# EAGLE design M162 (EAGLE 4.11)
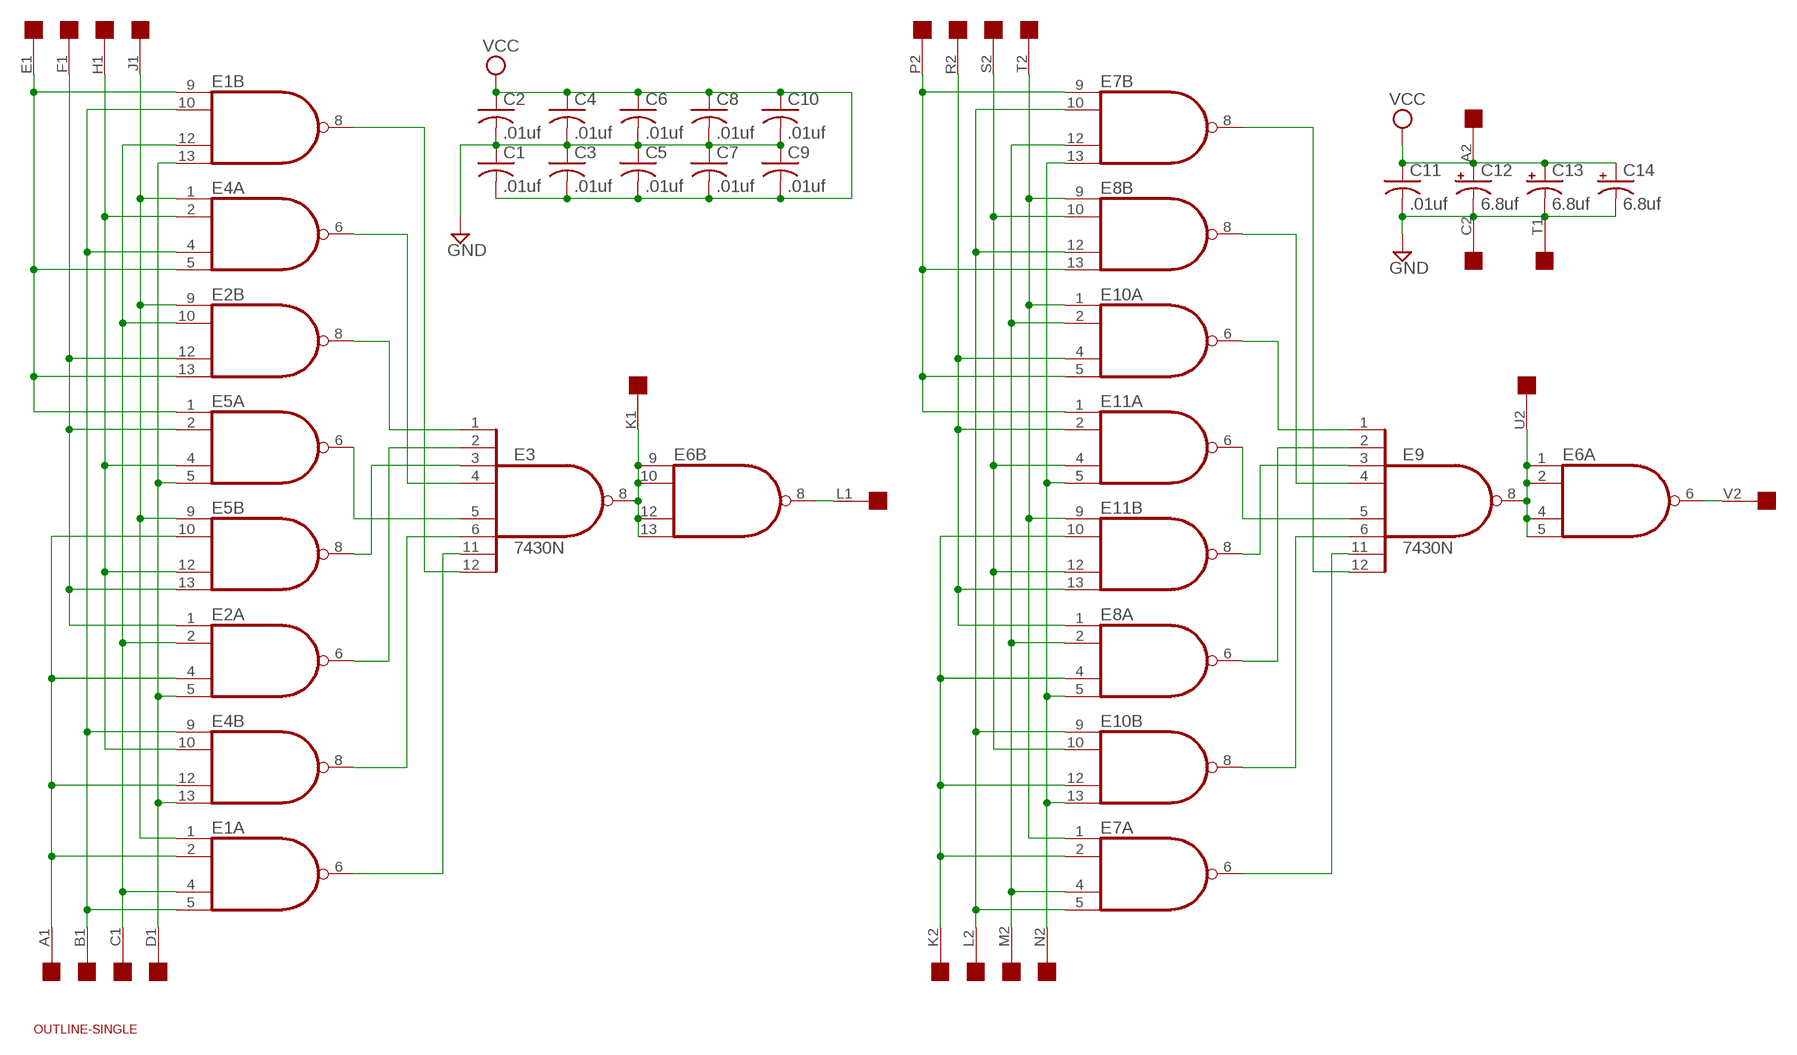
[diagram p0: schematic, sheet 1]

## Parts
C1  .01uf  C-US050-025X075  [C050-025X075]
C2  .01uf  C-US050-025X075  [C050-025X075]
C3  .01uf  C-US050-025X075  [C050-025X075]
C4  .01uf  C-US050-025X075  [C050-025X075]
C5  .01uf  C-US050-025X075  [C050-025X075]
C6  .01uf  C-US050-025X075  [C050-025X075]
C7  .01uf  C-US050-025X075  [C050-025X075]
C8  .01uf  C-US050-025X075  [C050-025X075]
C9  .01uf  C-US050-025X075  [C050-025X075]
C10  .01uf  C-US050-025X075  [C050-025X075]
C11  .01uf  C-US050-025X075  [C050-025X075]
C12  6.8uf  CPOL-USE22-6AXIAL  [E22-6]
C13  6.8uf  CPOL-USE22-6AXIAL  [E22-6]
C14  6.8uf  CPOL-USE22-6AXIAL  [E22-6]
E1  74S20N  [DIL14]
E2  74S20N  [DIL14]
E3  7430N  [DIL14]
E4  74S20N  [DIL14]
E5  74S20N  [DIL14]
E6  74S20N  [DIL14]
E7  74S20N  [DIL14]
E8  74S20N  [DIL14]
E9  7430N  [DIL14]
E10  74S20N  [DIL14]
E11  74S20N  [DIL14]
U$1  OUTLINE-SINGLE  [SINGLE]
U$2  EDGE-2CONNECTOR  [EDGE-CON2]

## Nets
GND: C1.1 C2.2 C3.1 C4.2 C5.1 C6.2 C7.1 C8.2 C9.1 C10.2 C11.2 C12.- C13.- C14.- U$2.C2 U$2.T1
N$1: E1.2(A:I1) E2.4(A:I2) E4.12(B:I2) E5.10(B:I1) U$2.A1
N$2: E1.13(B:I3) E2.5(A:I3) E4.13(B:I3) E5.5(A:I3) U$2.D1
N$3: E1.1(A:I0) E2.9(B:I0) E4.1(A:I0) E5.9(B:I0) U$2.J1
N$4: E4.2(A:I1) E4.10(B:I1) E5.4(A:I2) E5.12(B:I2) U$2.H1
N$5: E1.4(A:I2) E1.12(B:I2) E2.2(A:I1) E2.10(B:I1) U$2.C1
N$6: E1.5(A:I3) E1.10(B:I1) E4.4(A:I2) E4.9(B:I0) U$2.B1
N$7: E2.1(A:I0) E2.12(B:I2) E5.2(A:I1) E5.13(B:I3) U$2.F1
N$8: E1.9(B:I0) E2.13(B:I3) E4.5(A:I3) E5.1(A:I0) U$2.E1
N$9: E1.8(B:O) E3.12(I7)
N$10: E3.4(I3) E4.6(A:O)
N$11: E2.8(B:O) E3.1(I0)
N$12: E3.5(I4) E5.6(A:O)
N$13: E3.3(I2) E5.8(B:O)
N$14: E2.6(A:O) E3.2(I1)
N$15: E1.6(A:O) E3.11(I6)
N$16: E3.6(I5) E4.8(B:O)
N$17: E3.8(O) E6.9(B:I0) E6.10(B:I1) E6.12(B:I2) E6.13(B:I3) U$2.K1
N$18: E7.2(A:I1) E8.4(A:I2) E10.12(B:I2) E11.10(B:I1) U$2.K2
N$19: E7.13(B:I3) E8.5(A:I3) E10.13(B:I3) E11.5(A:I3) U$2.N2
N$20: E7.1(A:I0) E8.9(B:I0) E10.1(A:I0) E11.9(B:I0) U$2.T2
N$21: E8.10(B:I1) E10.10(B:I1) E11.4(A:I2) E11.12(B:I2) U$2.S2
N$22: E7.4(A:I2) E7.12(B:I2) E8.2(A:I1) E10.2(A:I1) U$2.M2
N$23: E7.5(A:I3) E7.10(B:I1) E8.12(B:I2) E10.9(B:I0) U$2.L2
N$24: E8.1(A:I0) E10.4(A:I2) E11.2(A:I1) E11.13(B:I3) U$2.R2
N$25: E7.9(B:I0) E8.13(B:I3) E10.5(A:I3) E11.1(A:I0) U$2.P2
N$26: E7.8(B:O) E9.12(I7)
N$27: E8.8(B:O) E9.4(I3)
N$28: E9.1(I0) E10.6(A:O)
N$29: E9.5(I4) E11.6(A:O)
N$30: E9.3(I2) E11.8(B:O)
N$31: E8.6(A:O) E9.2(I1)
N$32: E7.6(A:O) E9.11(I6)
N$33: E9.6(I5) E10.8(B:O)
N$34: E6.1(A:I0) E6.2(A:I1) E6.4(A:I2) E6.5(A:I3) E9.8(O) U$2.U2
N$35: E6.6(A:O) U$2.V2
N$36: E6.8(B:O) U$2.L1
VCC: C1.2 C2.1 C3.2 C4.1 C5.2 C6.1 C7.2 C8.1 C9.2 C10.1 C11.1 C12.+ C13.+ C14.+ U$2.A2
Unconnected: U$2.B2 U$2.D2 U$2.E2 U$2.F2 U$2.H2 U$2.J2 U$2.M1 U$2.N1 U$2.P1 U$2.R1 U$2.S1 U$2.U1 U$2.V1

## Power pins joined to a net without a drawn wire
GND: E1.7(P:GND) E2.7(P:GND) E3.7(GND) E4.7(P:GND) E5.7(P:GND) E6.7(P:GND) E7.7(P:GND) E8.7(P:GND) E9.7(GND) E10.7(P:GND) E11.7(P:GND)
VCC: E1.14(P:VCC) E2.14(P:VCC) E3.14(VCC) E4.14(P:VCC) E5.14(P:VCC) E6.14(P:VCC) E7.14(P:VCC) E8.14(P:VCC) E9.14(VCC) E10.14(P:VCC) E11.14(P:VCC)

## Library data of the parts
C1-C11 = rcl:C-US: CAPACITOR, American symbol
C12-C14 = rcl:CPOL-US: POLARIZED CAPACITOR, American symbol
E1 E2 E4-E8 E10 E11 = 74xx-jameco:74*20: Dual 4-input NAND gate
E3 E9 = 74xx-jameco:74*30: 8-input NAND gate
U$1 = dec-con:OUTLINE-*: Board outlines for DEC boards.
U$2 = dec-con:EDGE-2: Double-Sided DEC edge connector.

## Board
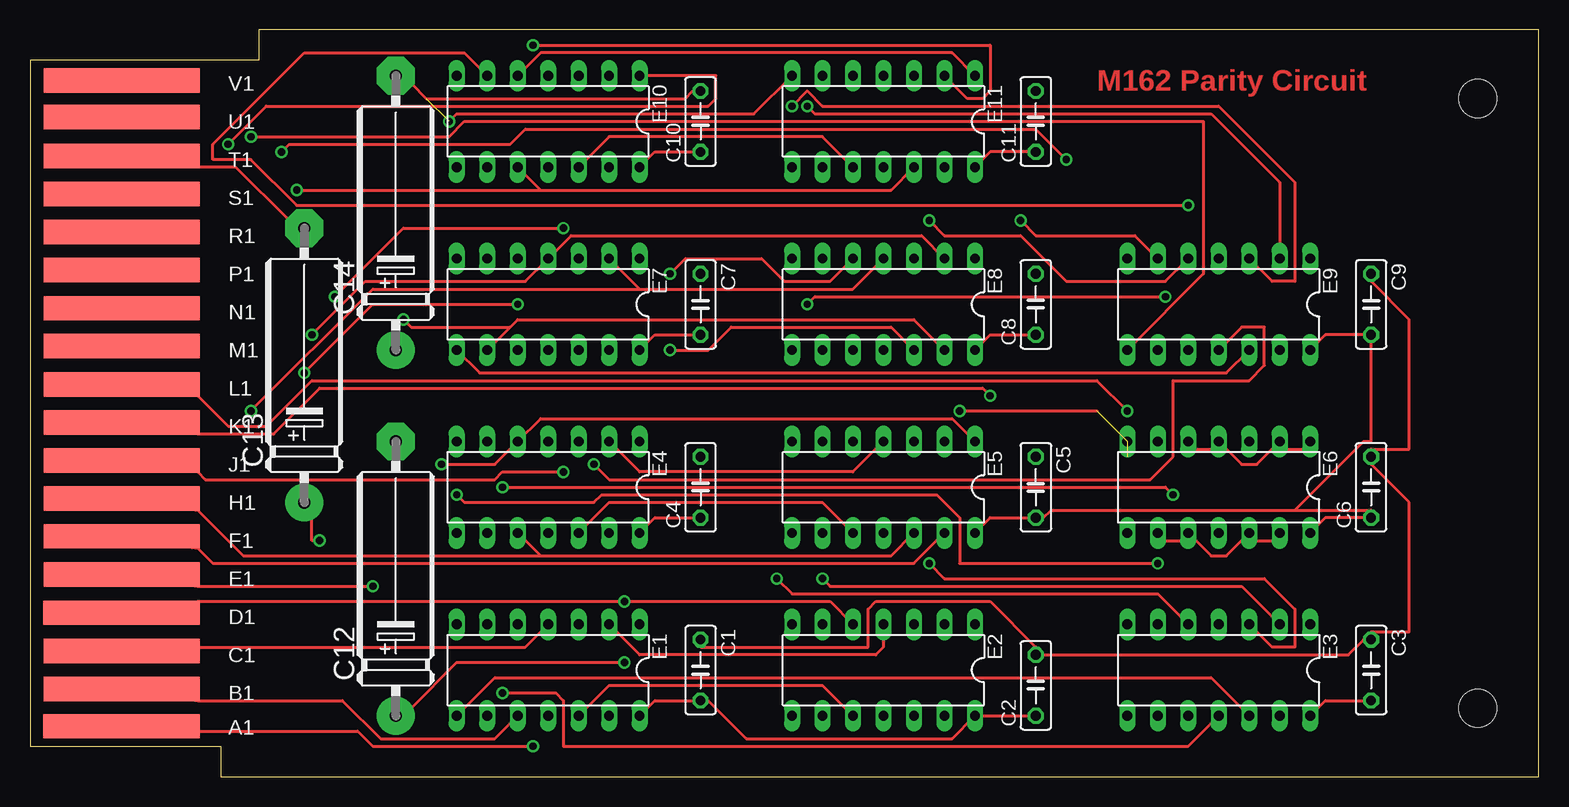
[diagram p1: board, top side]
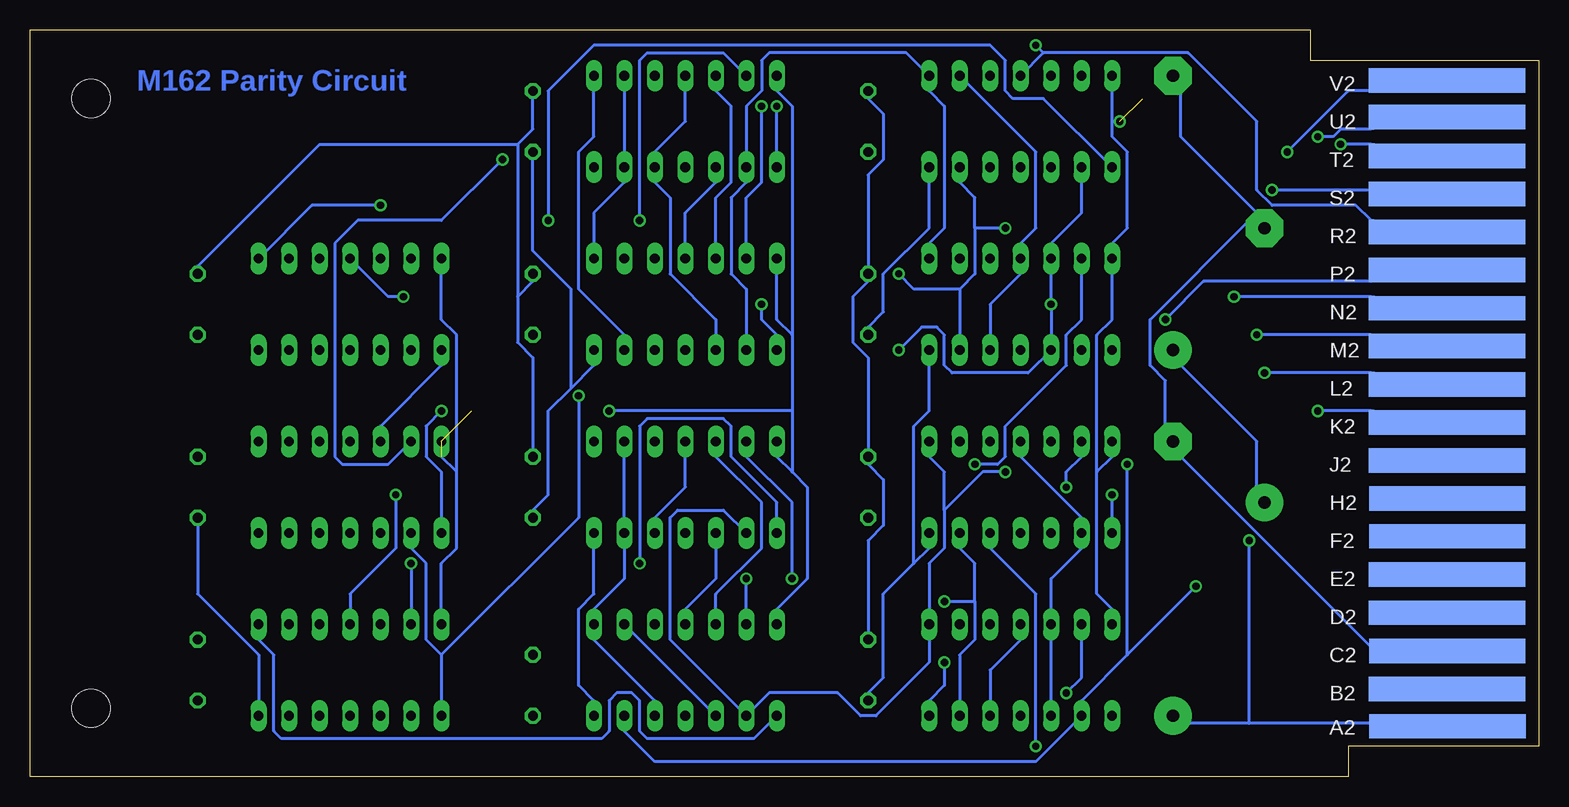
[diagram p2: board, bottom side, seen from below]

Size 125.73 x 62.23 mm. Coordinates in mm from the lower left corner, seen from the top.
Copper layers (1*16): Top 0.035mm / dielectric 1.5mm / Bottom 0.035mm
Design rules "default": minimum track width 10mil, minimum drill 24mil, track to track 8mil, track to pad 8mil, pad to pad 8mil, via to via 8mil, smd to smd 8mil, copper to edge 25mil, drill to drill 8mil, minimum pad ring 10mil, minimum via ring 8mil, stop-mask expansion 4mil, vias tented up to drill 0mil, thermal gap 10mil

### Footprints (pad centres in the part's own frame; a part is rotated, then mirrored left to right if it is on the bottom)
C050-025X075 = drill 0.813 octagon: 1 -2.54,0; 2 2.54,0
E22-6 = drill 1.016 pad 3.15 round: + -11.43,0 | drill 1.016 pad 3.15 octagon: - 11.43,0
DIL14 = drill 0.813 long: 1 -7.62,-3.81; 2 -5.08,-3.81; 3 -2.54,-3.81; 4 0,-3.81; 5 2.54,-3.81; 6 5.08,-3.81; 7 7.62,-3.81; 8 7.62,3.81; 9 5.08,3.81; 10 2.54,3.81; 11 0,3.81; 12 -2.54,3.81; 13 -5.08,3.81; 14 -7.62,3.81
SINGLE = hole 3.175: 120.65,56.515; 120.65,5.715
EDGE-CON2 = smd 13.017 x 2.032: A1 7.633,4.207; B1 7.639,7.327; C1 7.636,10.489; D1 7.633,13.665; E1 7.642,16.84; F1 7.642,20.041; H1 7.642,23.19; J1 7.642,26.34; K1 7.642,29.515; L1 7.642,32.69; M1 7.642,35.89; N1 7.642,39.04; P1 7.642,42.24; R1 7.642,45.39; S1 7.642,48.565; T1 7.642,51.74; U1 7.642,54.966; V1 7.642,58.026 | smd 13.017 x 2.032 bottom: A2 7.614,4.207; B2 7.642,7.328; C2 7.617,10.49; D2 7.642,13.665; E2 7.642,16.84; F2 7.617,20.041; H2 7.617,23.19; J2 7.642,26.34; K2 7.642,29.515; L2 7.642,32.69; M2 7.642,35.89; N2 7.642,39.04; P2 7.642,42.24; R2 7.642,45.39; S2 7.642,48.565; T2 7.642,51.74; U2 7.642,54.966; V2 7.642,58.026

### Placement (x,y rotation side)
C1  55.88,8.89 270 top
C2  83.82,7.62 90 top
C3  111.76,8.89 270 top
C4  55.88,24.13 90 top
C5  83.82,24.13 270 top
C6  111.76,24.13 90 top
C7  55.88,39.37 270 top
C8  83.82,39.37 90 top
C9  111.76,39.37 270 top
C10  55.88,54.61 90 top
C11  83.82,54.61 90 top
C12  30.48,16.51 90 top
C13  22.86,34.29 90 top
C14  30.48,46.99 90 top
E1  43.18,8.89 180 top
E2  71.12,8.89 180 top
E3  99.06,8.89 180 top
E4  43.18,24.13 180 top
E5  71.12,24.13 180 top
E6  99.06,24.13 180 top
E7  43.18,39.37 180 top
E8  71.12,39.37 180 top
E9  99.06,39.37 180 top
E10  43.18,54.61 180 top
E11  71.12,54.61 180 top
U$1  0,0 0 top
U$2  0,0 0 top

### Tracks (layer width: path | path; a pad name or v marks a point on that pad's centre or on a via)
GND  (via drill 0.61)  (3 unrouted)
  Top 0.254: C9.1 111.76,41.27 114.94,38.1 114.94,27.3 111.76,27.3 C6.2 111.76,26.04 114.94,22.86 114.94,12.06 111.76,12.06 C3.1 111.13,11.43 109.86,10.16 C2.2 83.82,10.79 80.01,14.61 70.49,14.61 69.85,13.97 69.85,10.79 55.88,10.79 C1.1 | C13.- 21.59,46.35 17.15,50.8 13.97,50.8 U$2.T1 | C10.2 55.25,57.15 54.61,56.52 33.02,56.52 31.75,57.78 C14.- | v77.47,30.48 88.9,30.48 | v34.93,54.61 35.56,55.24 60.33,55.24 E11.7
  Bottom 0.254: 85.09,40.01 85.09,36.2 83.82,34.92 C5.1 | 85.09,40.01 83.82,41.27 C8.2 | 85.09,52.7 83.82,53.98 C11.2 | 85.09,52.7 85.09,40.01 | 85.09,52.7 101.6,52.7 111.76,42.55 C9.1 | U$2.C2 13.97,10.79 29.85,26.67 C12.- 31.12,29.21 31.12,33.02 32.39,34.29 32.39,38.1 24.13,46.35 C13.- 23.5,46.99 29.85,53.34 29.85,57.15 C14.- | C1.1 55.88,19.68 54.61,20.95 54.61,24.77 55.88,26.04 C4.2 55.88,34.92 57.15,36.2 57.15,40.01 55.88,41.27 C7.1 55.88,50.16 54.61,51.44 54.61,55.24 55.88,56.52 C10.2 | 36.83,25.4 36.83,15.24 35.56,13.97 E1.7 | 36.83,25.4 35.56,26.67 E4.7 | 36.83,25.4 36.83,36.83 35.56,38.1 E7.7 35.56,44.45 34.29,45.72 34.29,52.07 35.56,53.34 35.56,54.61 | 35.56,54.61 E10.7 | 90.17,25.4 90.17,19.05 91.44,17.78 E3.7 | 90.17,25.4 91.44,26.67 | 90.17,25.4 90.17,36.83 91.44,38.1 E9.7 | 62.23,25.4 63.5,26.67 E5.7 | 62.23,25.4 60.96,24.13 60.96,16.51 63.5,13.97 E2.7 | 62.23,36.83 63.5,38.1 E8.7 | 62.23,30.48 62.23,25.4 | 62.23,36.83 62.23,30.48 | 62.23,36.83 62.23,55.88 63.5,57.15 E11.7 | 62.23,30.48 v77.47,30.48 | 35.56,54.61 v34.93,54.61
N$1  (via drill 0.61)
  Top 0.254: E4.12 48.26,22.86 66.04,22.86 E5.10 | E1.2 50.8,10.16 70.49,10.16 71.12,10.79 E2.4 | v41.91,2.54 28.58,2.54 27.31,3.81 13.97,3.81 U$2.A1
  Bottom 0.254: E5.10 68.58,16.51 71.12,13.97 E2.4 | v41.91,2.54 41.91,15.24 45.72,19.05 E4.12
N$2  (via drill 0.61)
  Top 0.254: E2.5 66.68,14.61 v49.53,14.61 13.97,14.61 U$2.D1
  Bottom 0.254: 46.99,14.61 46.99,17.78 48.26,19.05 E4.13 | 46.99,14.61 46.99,11.43 48.26,10.16 E1.13 | E2.5 68.58,15.24 64.77,19.05 64.77,22.86 68.58,26.67 E5.5 | v49.53,14.61 46.99,14.61
N$3  (via drill 0.61)
  Top 0.254: v44.45,25.4 39.37,25.4 38.74,24.77 14.61,24.77 13.97,25.4 U$2.J1
  Bottom 0.254: 49.53,22.23 49.53,25.4 50.8,26.67 E4.1 | 49.53,22.23 49.53,19.05 50.8,17.78 E1.1 50.8,9.53 55.25,5.08 56.52,5.08 58.42,6.99 64.14,6.99 E2.9 72.39,11.43 72.39,21.59 71.76,22.23 67.95,22.23 E5.9 | v44.45,25.4 46.36,25.4 49.53,22.23
N$4
  Top 0.254: E4.2 50.8,25.4 68.58,25.4 E5.4 | 42.55,18.41 71.76,18.41 E5.12 | 42.55,18.41 E4.10 | 42.55,18.41 17.78,18.41 13.97,22.23 U$2.H1
  Bottom 0.254: E5.4 71.12,24.13 73.66,21.59 E5.12
N$5
  Top 0.254: E1.4 41.28,10.79 13.97,10.79 U$2.C1 | E2.10 66.04,7.62 48.26,7.62 E1.12
  Bottom 0.254: E2.10 E2.2 | E1.12 45.72,8.89 43.18,11.43 E1.4
N$6
  Top 0.254: E1.10 38.74,3.17 29.21,3.17 26.04,6.35 13.97,6.35 U$2.B1
  Bottom 0.254: E1.10 E1.5 40.64,16.51 38.1,19.05 E4.9 38.1,21.59 43.18,26.67 E4.4
N$7
  Top 0.254: E5.13 73.66,17.78 15.24,17.78 13.97,19.05 U$2.F1
  Bottom 0.254: E5.2 E5.13 76.2,16.51 78.74,13.97 E2.1 78.74,11.43 73.66,6.35 E2.12
N$8  (via drill 0.61)
  Top 0.254: E5.1 76.84,29.84 42.55,29.84 E4.5 38.74,26.04 v34.29,26.04 | v28.58,15.88 13.97,15.88 U$2.E1
  Bottom 0.254: E2.13 76.2,3.81 73.66,1.27 41.91,1.27 E1.9 38.1,6.35 34.29,10.16 | v28.58,15.88 34.29,10.16 | 34.29,10.16 v34.29,26.04
N$9
  Top 0.254: E1.8 38.74,8.26 98.43,8.26 E3.12
N$10  (via drill 0.61)
  Top 0.254: v95.25,23.5 94.62,24.13 v39.37,24.13
  Bottom 0.254: v95.25,23.5 95.25,19.05 99.06,15.24 E3.4 | v39.37,24.13 39.37,25.4 38.1,26.67 E4.6
N$11
  Bottom 0.254: E2.8 65.41,3.17 74.3,3.17 74.93,3.81 74.93,6.35 75.57,6.99 76.84,6.99 77.47,6.35 77.47,3.81 78.11,3.17 104.78,3.17 105.41,3.81 105.41,10.16 106.68,11.43 E3.1
N$12  (via drill 0.61)
  Top 0.254: v62.23,16.51 63.5,15.24 93.98,15.24 E3.5
  Bottom 0.254: v62.23,16.51 62.23,22.86 66.04,26.67 E5.6
N$13  (via drill 0.61)
  Top 0.254: v74.93,17.78 76.2,16.51 102.87,16.51 105.41,13.97 105.41,10.79 103.51,10.79 E3.3
  Bottom 0.254: v74.93,17.78 74.93,29.21 74.3,29.84 67.95,29.84 67.31,29.21 67.31,26.67 63.5,22.86 E5.8
N$14  (via drill 0.61)
  Top 0.254: v66.04,16.51 66.68,15.88 100.97,15.88 E3.2
  Bottom 0.254: E2.6 v66.04,16.51
N$15  (via drill 0.61)
  Top 0.254: v39.37,6.99 43.82,6.99 44.45,6.35 44.45,2.54 96.52,2.54 E3.11
  Bottom 0.254: v39.37,6.99 38.1,8.26 E1.6
N$16  (via drill 0.61)
  Top 0.254: v35.56,23.5 36.2,22.86 46.99,22.86 47.63,23.5 75.57,23.5 77.47,21.59 77.47,17.78 v93.98,17.78
  Bottom 0.254: E4.8 v35.56,23.5 | v93.98,17.78 E3.6
N$17  (via drill 0.61)
  Top 0.254: E6.13 103.51,19.68 102.24,19.68 E6.12 99.7,18.41 98.43,18.41 E6.10 95.89,19.68 94.62,19.68 E6.9 | v80.01,31.75 79.38,32.38 24.13,32.38 20.32,28.57 13.97,28.57 U$2.K1
  Bottom 0.254: 91.44,10.16 92.71,11.43 92.71,17.78 93.98,19.05 E6.9 | 91.44,10.16 E3.8 | 91.44,10.16 80.01,21.59 v80.01,31.75
N$18  (via drill 0.61)
  Top 0.254: E10.12 48.26,53.34 66.04,53.34 E11.10 | 50.8,40.64 68.58,40.64 E8.4 | 50.8,40.64 E7.2 | v18.42,30.48 28.58,40.64 50.8,40.64
  Bottom 0.254: E11.10 68.58,49.53 71.12,46.99 E8.4 | v18.42,30.48 13.97,30.48 U$2.K2
N$19  (via drill 0.61)
  Top 0.254: v53.34,41.91 54.61,43.18 60.96,43.18 62.87,41.27 66.68,41.27 E8.5 | v25.4,40.01 31.12,45.72 v44.45,45.72
  Bottom 0.254: 48.26,40.64 46.99,41.91 46.99,45.72 | 46.99,45.72 46.99,48.26 48.26,49.53 E10.13 | 48.26,40.64 E7.13 | E8.5 68.58,48.26 67.31,49.53 67.31,55.88 68.58,57.15 E11.5 | 48.26,40.64 52.07,40.64 v53.34,41.91 | v25.4,40.01 13.97,40.01 U$2.N2 | v44.45,45.72 46.99,45.72
N$20  (via drill 0.61)
  Top 0.254: v16.51,52.7 19.69,55.88 56.52,55.88 57.15,56.52 57.15,58.42 E10.1
  Bottom 0.254: E8.9 66.04,40.64 67.31,41.91 67.31,48.26 66.04,49.53 E11.9 66.04,55.88 64.77,57.15 64.77,59.69 64.14,60.33 52.71,60.33 E10.1 50.8,57.15 49.53,55.88 49.53,45.72 50.8,44.45 E7.1 | v16.51,52.7 13.97,52.7 U$2.T2
N$21  (via drill 0.61)
  Top 0.254: 42.55,48.9 71.76,48.9 E11.12 | 42.55,48.9 E10.10 | v22.23,48.9 42.55,48.9
  Bottom 0.254: E8.10 68.58,38.1 72.39,41.91 72.39,48.26 73.66,49.53 E11.12 73.66,52.07 71.12,54.61 E11.4 | v22.23,48.9 13.97,48.9 U$2.S2
N$22  (via drill 0.61)
  Top 0.254: E8.2 74.3,45.09 45.09,45.09 E7.4 41.28,41.27 27.94,41.27 v23.5,36.83
  Bottom 0.254: E7.12 45.72,39.37 43.18,41.91 E7.4 43.18,44.45 41.91,45.72 41.91,52.07 E10.2 | v23.5,36.83 13.97,36.83 U$2.M2
N$23  (via drill 0.61)
  Top 0.254: v53.34,35.56 56.52,35.56 58.42,37.47 71.76,37.47 E8.12 | v22.86,33.66 28.58,39.37 v40.64,39.37
  Bottom 0.254: E10.9 38.1,46.99 40.64,44.45 E7.5 v40.64,39.37 E7.10 42.55,33.66 48.9,33.66 49.53,34.29 49.53,36.83 50.17,37.47 51.44,37.47 v53.34,35.56 | v22.86,33.66 13.97,33.66 U$2.L2
N$24  (via drill 0.61)
  Top 0.254: v41.91,60.96 80.01,60.96 80.01,57.15 79.38,56.52 78.11,56.52 E11.2
  Bottom 0.254: E11.2 E11.13 76.2,49.53 78.74,46.99 E8.1 | 41.28,60.33 29.21,60.33 23.5,54.61 23.5,48.9 22.23,47.62 15.24,47.62 13.97,46.35 U$2.R2 | 41.28,60.33 E10.4 | 41.28,60.33 v41.91,60.96
N$25  (via drill 0.61)
  Top 0.254: E10.5 42.55,60.33 76.84,60.33 E11.1 | 40.01,37.47 40.64,38.1 73.66,38.1 E8.13 | 40.01,37.47 E7.9 | v31.12,38.1 31.75,37.47 40.01,37.47
  Bottom 0.254: v31.12,38.1 27.94,41.27 13.97,41.27 U$2.P2 | E11.1 78.74,53.34 80.01,52.07 80.01,40.64 76.2,36.83 E8.13
N$26
  Top 0.254: E7.8 37.47,33.66 99.7,33.66 E9.12
N$27  (via drill 0.61)
  Top 0.254: v64.77,39.37 65.41,40.01 v94.62,40.01
  Bottom 0.254: v64.77,39.37 64.77,38.1 63.5,36.83 E8.8 | v94.62,40.01 95.89,40.01 E9.4
N$28  (via drill 0.61)
  Top 0.254: v96.52,47.62 22.23,47.62 18.42,51.44 15.24,51.44 15.24,52.7 22.86,60.33 36.2,60.33 E10.6
  Bottom 0.254: v96.52,47.62 102.24,47.62 E9.1
N$29  (via drill 0.61)
  Top 0.254: v74.93,46.35 76.2,45.09 82.55,45.09 86.36,41.27 94.62,41.27 E9.5
  Bottom 0.254: v74.93,46.35 74.93,59.69 74.3,60.33 67.95,60.33 E11.6
N$30  (via drill 0.61)
  Top 0.254: v63.5,55.88 64.77,57.15 66.04,55.88 99.06,55.88 105.41,49.53 105.41,41.27 103.51,41.27 E9.3
  Bottom 0.254: E11.8 v63.5,55.88
N$31  (via drill 0.61)
  Top 0.254: v64.77,55.88 65.41,55.24 98.43,55.24 104.14,49.53 E9.2
  Bottom 0.254: v64.77,55.88 64.77,49.53 66.04,48.26 E8.6
N$32  (via drill 0.61)
  Top 0.254: v46.99,26.04 48.26,24.77 93.35,24.77 95.25,26.67 95.25,33.02 101.6,33.02 102.87,34.29 102.87,37.47 100.97,37.47 E9.11
  Bottom 0.254: v46.99,26.04 45.09,26.04 44.45,26.67 44.45,29.21 39.37,34.29 39.37,36.83 38.1,38.1 E7.6
N$33  (via drill 0.61)
  Top 0.254: v82.55,46.35 83.82,45.09 92.08,45.09 E9.6
  Bottom 0.254: v82.55,46.35 82.55,57.15 78.74,60.96 45.72,60.96 44.45,59.69 44.45,57.15 43.82,56.52 41.28,56.52 E10.8
N$34  (via drill 0.61)
  Top 0.254: E6.1 106.05,27.3 104.78,27.3 E6.2 102.24,26.04 100.97,26.04 E6.4 98.43,27.3 97.16,27.3 E6.5 | v18.42,53.34 34.93,53.34 36.2,54.61 97.79,54.61 97.79,41.91 E9.8
  Bottom 0.254: E9.8 91.44,34.29 96.52,29.21 E6.5 | v18.42,53.34 17.15,53.34 16.51,53.98 13.97,53.98 U$2.U2
N$35  (via drill 0.61)
  Top 0.254: v86.36,51.44 83.82,53.98 41.28,53.98 40.01,52.7 21.59,52.7 v20.96,52.07
  Bottom 0.254: v86.36,51.44 91.44,46.35 98.43,46.35 100.33,44.45 100.33,26.67 99.7,26.04 95.89,26.04 E6.6 | v20.96,52.07 15.88,57.15 13.97,57.15 U$2.V2
N$36  (via drill 0.61)
  Top 0.254: v91.44,30.48 88.9,33.02 23.5,33.02 19.69,29.21 16.51,29.21 13.97,31.75 U$2.L1
  Bottom 0.254: v91.44,30.48 92.71,29.21 92.71,26.67 91.44,25.4 E6.8
VCC  (via drill 0.61)
  Top 0.254: E9.14 107.95,36.83 C9.2 111.76,27.94 111.13,27.94 105.41,22.23 | E3.14 107.95,6.35 C3.2 | E11.14 80.01,52.07 C11.1 | E8.14 80.01,36.83 C8.1 | E5.14 80.01,21.59 C5.2 84.46,21.59 85.09,22.23 105.41,22.23 | E6.14 107.95,21.59 C6.1 111.76,22.23 105.41,22.23 | v24.13,19.68 23.5,19.68 23.5,21.59 C13.+ | E10.14 52.07,52.07 C10.1 | E7.14 52.07,36.83 C7.2 | E4.14 52.07,21.59 C4.1 | C2.1 E2.14 76.84,3.17 59.69,3.17 56.52,6.35 C1.2 52.07,6.35 E1.14 | v49.53,9.53 35.56,9.53 31.75,5.71 C12.+
  Bottom 0.254: 80.65,32.38 82.55,30.48 82.55,23.5 83.82,22.23 C5.2 | 80.65,32.38 78.74,34.29 E8.14 | 80.65,32.38 80.65,40.64 83.82,43.81 C11.1 | E3.14 106.68,10.16 111.76,15.24 C6.1 | C13.+ 23.5,24.13 23.5,27.94 29.85,34.29 C14.+ | 24.13,4.45 13.97,4.45 U$2.A2 | 24.13,4.45 29.21,4.45 C12.+ | 24.13,4.45 v24.13,19.68 | 52.07,17.78 54.61,15.24 54.61,8.26 55.88,6.99 C1.2 | 52.07,17.78 50.8,19.05 E4.14 | 52.07,17.78 52.07,29.21 50.8,30.48 E7.14 | E10.14 50.8,45.72 54.61,41.91 54.61,38.73 55.88,37.47 C7.2 | v49.53,9.53 49.53,7.62 50.8,6.35 E1.14 | E5.14 78.74,15.24 80.01,13.97 80.01,7.62 78.74,6.35 E2.14

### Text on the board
Top: M162 Parity Circuit
Bottom: M162 Parity Circuit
